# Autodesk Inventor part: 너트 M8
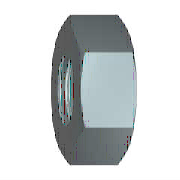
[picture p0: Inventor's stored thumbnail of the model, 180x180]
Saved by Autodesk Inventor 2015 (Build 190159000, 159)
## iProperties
IsCustomPart: 1
Created: 2012-02
Part Number: 너트 M8
Material: 강철, 연강
Description: 6각 너트 및 6각 가는 너트
Document SubType Name: Modeling
Standard: KS B 1012
Designer: mduedu
Standards Organization: KS
Language: ko-KR
Size Designation: M 8
Categories: <MemberInstance><Categories><Category DisplayName="조임쇠" InternalName="e4da775c-781d-43d5-af7c-5136215cf5a6" Mnemonic="FSTN"><Category DisplayName="너트" InternalN
Density: 1 g/cm^3
Appearance: 강철
Author: mduedu
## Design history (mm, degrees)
sketch "스케치1"
  geometry: L1 (-7.506, 0)-(-3.753, 6.5); L2 (-3.753, 6.5)-(3.753, 6.5); L3 (3.753, 6.5)-(7.506, 0); L4 (7.506, 0)-(3.753, -6.5); L5 (3.753, -6.5)-(-3.753, -6.5); L6 (-3.753, -6.5)-(-7.506, 0); 2 further points
  constraints: 12 end point, 1 coincident, 1 horizontal, 11 other
  dimensions: "d0" = 15.01111 distance of L3.end L1.start (= 1.1547 x SW)
extrude "본체" new body sketch "스케치1" distance "d1" = 5 (= KOH); taper "d2" = 0 deg
sketch "스케치2"
  geometry: L1 (0, 3.753)-(0, 7.506) reference; L2 (0, 7.506)-(5, 7.506) reference; L3 (5, 3.753)-(5, 7.506) reference; L4 (-1, 0)-(6, 0) reference; L5 (0.581, 7.506)-(0, 6.5); L6 (4.419, 7.506)-(5, 6.5)
  constraints: 4 end point, 4 point on line
  dimensions: "d3" = 30 deg angle of L1 L5 (= ANG1); "d4" = 30 deg angle of L3 L6 (= ANG2); "d5" = 13 diameter of L5.end L4 (= SW0); "d6" = 13 diameter of L6.end L4 (= SW01)
revolve "모따기1" sketch "스케치2" stored, may be unused: angle "d7" = 90 deg
sketch "스케치3"
  geometry: A1 r 6.5 centre (0, 0) between (-3.25, -5.629) and (3.25, -5.629) reference; 1 further point
  constraints: 1 coincident
hole "스레드" sketch "스케치3" at (0, 0) diameter "d25" = 6.647; stored, may be unused: countersink angle "d29" = 82 deg, drill point angle "d31" = 118 deg; dims "d26" = 6, "d27" = 4, "d28" = 2, "d30" = 8
workaxis "Work Axis1"
workplane "Work Plane1"
body "Solid1"
chamfer "모따기2" distance "d8" = 0.67658 (= -0.5 x GD1 + 0.5 x NND); stored, may be unused: angle "d9" = 30 deg, second distance "d40" = 0.67658 (= -0.5 x GD1 + 0.5 x NND)
chamfer "모따기3" distance "d10" = 0.67658 (= -0.5 x GD1 + 0.5 x NND); stored, may be unused: angle "d11" = 30 deg, second distance "d41" = 0.67658 (= -0.5 x GD1 + 0.5 x NND)
other parameters: "ANG1" = 30 deg [user parameter; used in 1 equation term], "ANG2" = 30 deg [user parameter; used in 1 equation term], "NND" = 8 [user parameter; used in 4 equation terms], "KOH" = 5 [user parameter; used in 1 equation term], "SW" = 13 [user parameter; used in 4 equation terms], "SW0" = 13 (= SW) [user parameter; used in 1 equation term], "SW01" = 13 (= SW) [user parameter; used in 1 equation term], "GD1" = 6.64684 (computed from THREADDIA, PTC, TOA) [user parameter; used in 4 equation terms], "d13" = 0, "d14" = 0, "d39" = 0, "d42" = 0, "GUL" = 0.67658 (= 0.541266 x PTC) [user parameter], "TPU" = 8 (computed from PTC) [user parameter], "THREADDIA" = 8 [user parameter; used in 1 equation term], "TOA" = 30 deg [user parameter; used in 1 equation term], "PTC" = 1.25 [user parameter; used in 4 equation terms], "E0" = 15.015 (= 1.155 x SW) [user parameter], "GAL" = 0.67658 (= 0.541266 x PTC) [user parameter]
